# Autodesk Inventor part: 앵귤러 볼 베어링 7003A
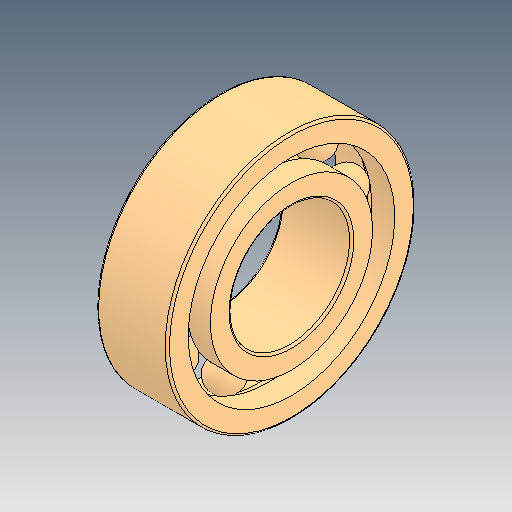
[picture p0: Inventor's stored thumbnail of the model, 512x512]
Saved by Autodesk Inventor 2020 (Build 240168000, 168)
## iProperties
Created: 2024-11
Part Number: 앵귤러 볼 베어링 7003A
Material: 강철, 연강
Description: 앵귤러 콘택트 볼 베어링
Document SubType Name: Modeling
Designer: shin
Density: 7.85 g/cm^3
Appearance: 기본값
Author: jhkim
Sending System: Autodesk Inventor 2025
Preprocessor: ST-DEVELOPER v20
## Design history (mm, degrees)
feature "Solid1"
feature "Solid1:1"
feature "Solid1:2"
feature "Solid1:3"
feature "Solid1:4"
feature "Solid1:5"
feature "Solid1:6"
feature "Solid1:7"
feature "Solid1:8"
feature "Solid1:9"
feature "Solid1:10"
node "솔리드1"
node "솔리드2"
node "솔리드3"
node "솔리드4"
node "솔리드5"
node "솔리드6"
node "솔리드7"
node "솔리드8"
node "솔리드9"
node "솔리드10"
node "솔리드11"
